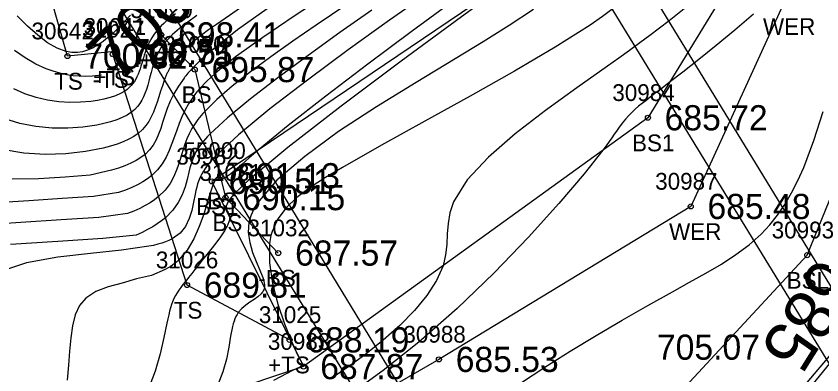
# Model space of a CAD drawing. Extents: x 1376587 to 1378239, y 1000335 to 1003031.
# Drawn here: x 1377325.31 to 1377373.31, y 1001668.9 to 1001690.3 of the extents above; entities that cross this region are included whole.
import ezdxf

# ---------------------------------------------------------------- set-up
doc = ezdxf.new("R2010")
doc.units = 0
for name, color, linetype in [('RD_DTM_BkLn2', 7, 'Continuous'), ('RD_DTM_BkLn_txCode', 7, 'Continuous'), ('RD_DTM_Major1', 7, 'Continuous'), ('RD_DTM_Major1_Lbl', 7, 'Continuous'), ('RD_DTM_Minor1', 7, 'Continuous'), ('RD_EX_Bridge', 7, 'Continuous'), ('RD_EX_H2O', 7, 'Continuous'), ('RD_EX_H2O_txCode', 7, 'Continuous'), ('RD_EX_TX_DV_Prop_ELEV', 7, 'Continuous'), ('RD_EX_TX_H2O_ELEV', 7, 'Continuous'), ('RD_EX_TX_Misc_ELEV', 7, 'Continuous'), ('RD_SMD_Locator', 7, 'Continuous')]:
    doc.layers.add(name, color=color, linetype=linetype)

msp = doc.modelspace()

# ---------------------------------------------------------------- linework, layer by layer
at = {"layer": 'RD_DTM_BkLn2'}
for points in [[(1377331.185, 1001688.178), (1377328.363, 1001687.912), (1377326.336, 1001695.068), (1377322.001, 1001703.779), (1377308.607, 1001727.47), (1377286.368, 1001761.867), (1377261.456, 1001806.931)], [(1377365.624, 1001716.092), (1377370.663, 1001706.746), (1377362.502, 1001698.7), (1377359.368, 1001695.61), (1377337.465, 1001680.779), (1377336.97, 1001680.444), (1377342.423, 1001669.398)], [(1377322.969, 1001642.525), (1377338.521, 1001652.749), (1377349.324, 1001661.46), (1377362.701, 1001665.53), (1377372.438, 1001676.042), (1377380.468, 1001695.811), (1377383.451, 1001707.403)], [(1377333.955, 1001689.179), (1377335.945, 1001687.109), (1377337.465, 1001680.779), (1377337.779, 1001679.474), (1377340.925, 1001676.168)], [(1377341.6, 1001670.994), (1377335.487, 1001674.258), (1377331.067, 1001688.02)]]:
    msp.add_lwpolyline(points, dxfattribs=at)
at = {"layer": 'RD_DTM_Major1'}
for points in [[(1377355.023, 1001692.574), (1377351.835, 1001690.259), (1377348.253, 1001687.62), (1377344.676, 1001684.93), (1377341.501, 1001682.461), (1377339.128, 1001680.486), (1377338.853, 1001680.237), (1377338.608, 1001680.007), (1377338.396, 1001679.797), (1377338.217, 1001679.606), (1377338.071, 1001679.434), (1377337.962, 1001679.282), (1377337.893, 1001679.161), (1377337.85, 1001679.054), (1377337.829, 1001678.959), (1377337.827, 1001678.874), (1377337.84, 1001678.797), (1377337.863, 1001678.725), (1377337.895, 1001678.656), (1377337.93, 1001678.588), (1377337.966, 1001678.52), (1377337.997, 1001678.45), (1377338.02, 1001678.375), (1377338.032, 1001678.293), (1377338.032, 1001678.262), (1377338.031, 1001678.229), (1377338.027, 1001678.195), (1377338.021, 1001678.159), (1377338.014, 1001678.123), (1377338.005, 1001678.086), (1377337.895, 1001677.806), (1377337.715, 1001677.486), (1377337.481, 1001677.135), (1377337.206, 1001676.761), (1377336.905, 1001676.375), (1377336.592, 1001675.983), (1377336.377, 1001675.715), (1377336.166, 1001675.452), (1377335.961, 1001675.196), (1377335.765, 1001674.95), (1377335.581, 1001674.717), (1377335.409, 1001674.501), (1377335.381, 1001674.465), (1377335.353, 1001674.43), (1377335.326, 1001674.395), (1377335.299, 1001674.36), (1377335.272, 1001674.326), (1377335.246, 1001674.293), (1377335.119, 1001674.124), (1377335.002, 1001673.96), (1377334.896, 1001673.797), (1377334.799, 1001673.631), (1377334.711, 1001673.456), (1377334.631, 1001673.268), (1377334.567, 1001673.092), (1377334.508, 1001672.902), (1377334.451, 1001672.697), (1377334.397, 1001672.477), (1377334.342, 1001672.24), (1377334.287, 1001671.985), (1377334.108, 1001671.137), (1377333.882, 1001670.169), (1377333.582, 1001669.12), (1377333.179, 1001668.032)], [(1377343.945, 1001691.663), (1377341.876, 1001690.298), (1377339.997, 1001689.022), (1377339.184, 1001688.45), (1377338.442, 1001687.907), (1377337.772, 1001687.39), (1377337.178, 1001686.894), (1377336.661, 1001686.417), (1377336.223, 1001685.953), (1377336.15, 1001685.868), (1377336.08, 1001685.783), (1377336.012, 1001685.699), (1377335.947, 1001685.614), (1377335.885, 1001685.53), (1377335.824, 1001685.445), (1377335.575, 1001685.06), (1377335.364, 1001684.673), (1377335.182, 1001684.286), (1377335.022, 1001683.897), (1377334.877, 1001683.506), (1377334.738, 1001683.113), (1377334.591, 1001682.698), (1377334.429, 1001682.286), (1377334.241, 1001681.883), (1377334.013, 1001681.495), (1377333.734, 1001681.129), (1377333.389, 1001680.789), (1377333.135, 1001680.592), (1377332.85, 1001680.408), (1377332.535, 1001680.234), (1377332.191, 1001680.071), (1377331.817, 1001679.917), (1377331.414, 1001679.771), (1377329.914, 1001679.539), (1377328.049, 1001679.415), (1377326.06, 1001679.286), (1377324.131, 1001679.161)], [(1377330.384, 1001686.776), (1377330.22, 1001686.749), (1377329.852, 1001686.713), (1377329.463, 1001686.701), (1377329.091, 1001686.711), (1377328.707, 1001686.745), (1377328.315, 1001686.804), (1377327.915, 1001686.891), (1377327.51, 1001687.006), (1377327.102, 1001687.153), (1377326.471, 1001687.442), (1377325.839, 1001687.806), (1377325.206, 1001688.243)], [(1377355.359, 1001668.403), (1377356.808, 1001669.364), (1377358.319, 1001670.32), (1377359.864, 1001671.26), (1377361.413, 1001672.172), (1377362.938, 1001673.044), (1377364.411, 1001673.866), (1377365.431, 1001674.426), (1377366.403, 1001674.971), (1377367.321, 1001675.514), (1377368.178, 1001676.073), (1377368.969, 1001676.664), (1377369.689, 1001677.303), (1377370.202, 1001677.849), (1377370.672, 1001678.438), (1377371.104, 1001679.072), (1377371.503, 1001679.756), (1377371.875, 1001680.49), (1377372.225, 1001681.28), (1377372.825, 1001682.875), (1377373.386, 1001684.602)]]:
    msp.add_lwpolyline(points, dxfattribs=at)
at = {"layer": 'RD_DTM_Minor1'}
for points in [[(1377349.9, 1001691.702), (1377347.559, 1001690.057), (1377345.093, 1001688.284), (1377342.663, 1001686.484), (1377340.428, 1001684.76), (1377338.549, 1001683.213), (1377337.185, 1001681.946), (1377337, 1001681.748), (1377336.837, 1001681.561), (1377336.694, 1001681.384), (1377336.569, 1001681.214), (1377336.461, 1001681.05), (1377336.367, 1001680.889), (1377336.268, 1001680.691), (1377336.186, 1001680.494), (1377336.118, 1001680.296), (1377336.062, 1001680.097), (1377336.014, 1001679.894), (1377335.972, 1001679.686), (1377335.883, 1001679.201), (1377335.778, 1001678.706), (1377335.624, 1001678.232), (1377335.401, 1001677.762), (1377335.069, 1001677.354), (1377334.601, 1001677.016), (1377334.412, 1001676.923), (1377334.204, 1001676.838), (1377333.98, 1001676.762), (1377333.74, 1001676.692), (1377333.483, 1001676.629), (1377333.211, 1001676.572), (1377331.591, 1001676.339), (1377329.731, 1001676.151), (1377327.79, 1001675.928), (1377325.928, 1001675.59), (1377324.303, 1001675.055)], [(1377345.01, 1001690.998), (1377343.186, 1001689.766), (1377341.791, 1001688.804), (1377340.474, 1001687.867), (1377339.262, 1001686.968), (1377338.184, 1001686.119), (1377337.268, 1001685.331), (1377336.543, 1001684.617), (1377336.432, 1001684.493), (1377336.327, 1001684.372), (1377336.229, 1001684.252), (1377336.138, 1001684.135), (1377336.052, 1001684.019), (1377335.973, 1001683.904), (1377335.779, 1001683.592), (1377335.618, 1001683.283), (1377335.482, 1001682.975), (1377335.365, 1001682.665), (1377335.261, 1001682.35), (1377335.163, 1001682.03), (1377335.035, 1001681.604), (1377334.888, 1001681.172), (1377334.708, 1001680.741), (1377334.476, 1001680.319), (1377334.177, 1001679.913), (1377333.793, 1001679.532), (1377333.555, 1001679.345), (1377333.288, 1001679.166), (1377332.995, 1001678.995), (1377332.674, 1001678.831), (1377332.326, 1001678.673), (1377331.951, 1001678.521), (1377330.227, 1001678.287), (1377327.982, 1001678.142), (1377325.583, 1001677.985), (1377323.221, 1001677.833)], [(1377338.987, 1001691), (1377337.24, 1001689.806), (1377336.775, 1001689.472), (1377336.349, 1001689.156), (1377335.965, 1001688.856), (1377335.621, 1001688.57), (1377335.318, 1001688.296), (1377335.058, 1001688.032), (1377334.91, 1001687.863), (1377334.778, 1001687.698), (1377334.661, 1001687.534), (1377334.557, 1001687.373), (1377334.464, 1001687.211), (1377334.38, 1001687.05), (1377334.357, 1001687.004), (1377334.335, 1001686.958), (1377334.314, 1001686.912), (1377334.293, 1001686.866), (1377334.273, 1001686.82), (1377334.253, 1001686.774), (1377334.129, 1001686.458), (1377334.017, 1001686.139), (1377333.913, 1001685.817), (1377333.812, 1001685.493), (1377333.708, 1001685.17), (1377333.596, 1001684.848), (1377333.485, 1001684.566), (1377333.359, 1001684.29), (1377333.211, 1001684.022), (1377333.036, 1001683.767), (1377332.828, 1001683.527), (1377332.581, 1001683.305), (1377332.318, 1001683.12), (1377332.019, 1001682.952), (1377331.687, 1001682.799), (1377331.322, 1001682.662), (1377330.926, 1001682.537), (1377330.5, 1001682.426), (1377329.439, 1001682.218), (1377328.272, 1001682.088), (1377327.032, 1001682.054), (1377325.756, 1001682.135), (1377324.48, 1001682.35)], [(1377340.748, 1001691.063), (1377338.499, 1001689.47), (1377336.674, 1001688.012), (1377336.52, 1001687.875), (1377336.371, 1001687.74), (1377336.229, 1001687.606), (1377336.093, 1001687.475), (1377335.963, 1001687.346), (1377335.839, 1001687.219), (1377335.762, 1001687.136), (1377335.687, 1001687.054), (1377335.615, 1001686.973), (1377335.545, 1001686.893), (1377335.478, 1001686.813), (1377335.413, 1001686.734), (1377335.395, 1001686.712), (1377335.377, 1001686.689), (1377335.36, 1001686.667), (1377335.342, 1001686.645), (1377335.325, 1001686.623), (1377335.308, 1001686.601), (1377334.971, 1001686.123), (1377334.702, 1001685.662), (1377334.487, 1001685.216), (1377334.313, 1001684.784), (1377334.167, 1001684.364), (1377334.036, 1001683.955), (1377333.921, 1001683.6), (1377333.797, 1001683.256), (1377333.652, 1001682.926), (1377333.476, 1001682.612), (1377333.257, 1001682.318), (1377332.985, 1001682.047), (1377332.739, 1001681.859), (1377332.456, 1001681.686), (1377332.14, 1001681.525), (1377331.789, 1001681.375), (1377331.406, 1001681.237), (1377330.992, 1001681.108), (1377329.713, 1001680.805), (1377328.223, 1001680.696), (1377326.641, 1001680.595), (1377325.08, 1001680.575)], [(1377351.355, 1001691.217), (1377348.847, 1001689.368), (1377346.252, 1001687.429), (1377343.748, 1001685.523), (1377341.511, 1001683.773), (1377339.717, 1001682.304), (1377339.192, 1001681.85), (1377338.748, 1001681.458), (1377338.378, 1001681.134), (1377338.076, 1001680.881), (1377337.835, 1001680.706), (1377337.649, 1001680.613), (1377337.622, 1001680.606), (1377337.596, 1001680.601), (1377337.572, 1001680.599), (1377337.549, 1001680.6), (1377337.527, 1001680.603), (1377337.506, 1001680.61), (1377337.482, 1001680.626), (1377337.458, 1001680.643), (1377337.434, 1001680.66), (1377337.41, 1001680.676), (1377337.387, 1001680.693), (1377337.363, 1001680.71), (1377337.322, 1001680.717), (1377337.28, 1001680.702), (1377337.238, 1001680.665), (1377337.194, 1001680.608), (1377337.149, 1001680.531), (1377337.102, 1001680.433), (1377337.068, 1001680.351), (1377337.032, 1001680.259), (1377336.996, 1001680.157), (1377336.959, 1001680.046), (1377336.92, 1001679.926), (1377336.88, 1001679.798), (1377336.697, 1001679.189), (1377336.479, 1001678.489), (1377336.212, 1001677.748), (1377335.886, 1001677.014), (1377335.487, 1001676.334), (1377335.005, 1001675.758), (1377334.88, 1001675.645), (1377334.751, 1001675.539), (1377334.616, 1001675.44), (1377334.477, 1001675.348), (1377334.334, 1001675.262), (1377334.187, 1001675.182), (1377333.371, 1001674.84), (1377332.487, 1001674.626), (1377331.623, 1001674.372), (1377330.791, 1001674.15), (1377330.052, 1001673.87), (1377329.455, 1001673.484), (1377329.081, 1001673.033), (1377328.825, 1001672.478), (1377328.659, 1001671.832), (1377328.556, 1001671.107), (1377328.487, 1001670.317), (1377328.427, 1001669.474), (1377328.349, 1001668.592)], [(1377346.499, 1001690.644), (1377344.592, 1001689.314), (1377342.695, 1001687.957), (1377340.891, 1001686.624), (1377339.264, 1001685.367), (1377337.894, 1001684.235), (1377336.864, 1001683.281), (1377336.716, 1001683.127), (1377336.582, 1001682.98), (1377336.461, 1001682.838), (1377336.351, 1001682.701), (1377336.253, 1001682.568), (1377336.164, 1001682.438), (1377336.021, 1001682.198), (1377335.905, 1001681.962), (1377335.81, 1001681.726), (1377335.73, 1001681.488), (1377335.662, 1001681.245), (1377335.599, 1001680.993), (1377335.496, 1001680.561), (1377335.372, 1001680.109), (1377335.203, 1001679.645), (1377334.966, 1001679.179), (1377334.639, 1001678.719), (1377334.197, 1001678.274), (1377333.97, 1001678.091), (1377333.718, 1001677.913), (1377333.441, 1001677.738), (1377333.14, 1001677.567), (1377332.814, 1001677.4), (1377332.464, 1001677.236), (1377330.469, 1001677.034), (1377327.793, 1001676.859), (1377324.963, 1001676.675)], [(1377356.122, 1001690.699), (1377354.688, 1001689.747), (1377353.132, 1001688.769), (1377351.468, 1001687.754), (1377349.137, 1001686.348), (1377346.773, 1001684.892), (1377344.512, 1001683.415), (1377342.508, 1001681.936), (1377340.828, 1001680.514), (1377339.675, 1001679.147), (1377339.555, 1001678.954), (1377339.45, 1001678.761), (1377339.36, 1001678.57), (1377339.284, 1001678.381), (1377339.224, 1001678.191), (1377339.179, 1001678.003), (1377339.138, 1001677.39), (1377339.224, 1001676.789), (1377339.396, 1001676.208), (1377339.611, 1001675.66), (1377339.828, 1001675.155), (1377340.005, 1001674.704), (1377340.04, 1001674.592), (1377340.068, 1001674.485), (1377340.089, 1001674.383), (1377340.101, 1001674.287), (1377340.104, 1001674.195), (1377340.097, 1001674.109), (1377340.083, 1001674.039), (1377340.06, 1001673.973), (1377340.031, 1001673.911), (1377339.995, 1001673.851), (1377339.952, 1001673.793), (1377339.904, 1001673.738), (1377339.713, 1001673.568), (1377339.484, 1001673.406), (1377339.235, 1001673.241), (1377338.983, 1001673.063), (1377338.746, 1001672.862), (1377338.542, 1001672.627), (1377338.466, 1001672.51), (1377338.399, 1001672.384), (1377338.34, 1001672.25), (1377338.288, 1001672.107), (1377338.242, 1001671.957), (1377338.2, 1001671.799), (1377338.082, 1001671.211), (1377337.97, 1001670.552), (1377337.83, 1001669.839), (1377337.626, 1001669.089), (1377337.32, 1001668.318)], [(1377360.883, 1001690.752), (1377360.234, 1001690.27), (1377359.5, 1001689.762), (1377357.423, 1001688.445), (1377354.989, 1001687.015), (1377352.352, 1001685.526), (1377349.664, 1001684.036), (1377347.08, 1001682.602), (1377344.751, 1001681.279), (1377343.73, 1001680.672), (1377342.822, 1001680.084), (1377342.039, 1001679.491), (1377341.392, 1001678.872), (1377340.894, 1001678.203), (1377340.555, 1001677.46), (1377340.519, 1001677.343), (1377340.487, 1001677.224), (1377340.459, 1001677.103), (1377340.434, 1001676.979), (1377340.413, 1001676.852), (1377340.397, 1001676.723), (1377340.394, 1001675.59), (1377340.584, 1001674.359), (1377340.906, 1001673.114), (1377341.299, 1001671.941), (1377341.702, 1001670.923), (1377342.052, 1001670.148), (1377342.071, 1001670.107), (1377342.091, 1001670.068), (1377342.11, 1001670.03), (1377342.128, 1001669.993), (1377342.146, 1001669.959), (1377342.163, 1001669.925), (1377342.195, 1001669.863), (1377342.225, 1001669.807), (1377342.253, 1001669.756), (1377342.278, 1001669.71), (1377342.3, 1001669.67), (1377342.319, 1001669.633), (1377342.345, 1001669.582), (1377342.362, 1001669.539), (1377342.371, 1001669.505), (1377342.37, 1001669.476), (1377342.36, 1001669.452), (1377342.34, 1001669.43), (1377342.299, 1001669.404), (1377342.24, 1001669.377), (1377342.163, 1001669.345), (1377342.064, 1001669.305), (1377341.945, 1001669.255), (1377341.803, 1001669.19), (1377340.641, 1001668.561)], [(1377365.104, 1001690.732), (1377364.204, 1001690.023), (1377363.639, 1001689.588), (1377363.059, 1001689.147), (1377362.462, 1001688.7), (1377361.846, 1001688.245), (1377361.208, 1001687.781), (1377360.546, 1001687.305), (1377358.72, 1001686.012), (1377356.843, 1001684.66), (1377355.042, 1001683.277), (1377353.442, 1001681.89), (1377352.171, 1001680.527), (1377351.355, 1001679.215), (1377351.142, 1001678.566), (1377351.037, 1001677.933), (1377350.991, 1001677.307), (1377350.957, 1001676.682), (1377350.89, 1001676.053), (1377350.741, 1001675.413), (1377350.359, 1001674.537), (1377349.781, 1001673.643), (1377349.038, 1001672.743), (1377348.161, 1001671.85), (1377347.182, 1001670.977), (1377346.132, 1001670.136), (1377345.121, 1001669.396), (1377344.078, 1001668.685)], [(1377336.081, 1001690.335), (1377335.526, 1001689.936), (1377335.038, 1001689.557), (1377334.621, 1001689.195), (1377334.276, 1001688.845), (1377334.091, 1001688.621), (1377333.934, 1001688.4), (1377333.803, 1001688.182), (1377333.694, 1001687.966), (1377333.602, 1001687.752), (1377333.523, 1001687.539), (1377333.503, 1001687.479), (1377333.484, 1001687.419), (1377333.465, 1001687.359), (1377333.447, 1001687.299), (1377333.43, 1001687.239), (1377333.412, 1001687.179), (1377333.344, 1001686.926), (1377333.278, 1001686.674), (1377333.213, 1001686.423), (1377333.144, 1001686.175), (1377333.068, 1001685.931), (1377332.982, 1001685.69), (1377332.894, 1001685.482), (1377332.793, 1001685.28), (1377332.674, 1001685.085), (1377332.534, 1001684.9), (1377332.37, 1001684.725), (1377332.177, 1001684.563), (1377331.921, 1001684.394), (1377331.626, 1001684.243), (1377331.296, 1001684.108), (1377330.933, 1001683.99), (1377330.539, 1001683.888), (1377330.119, 1001683.8), (1377329.286, 1001683.678), (1377328.39, 1001683.615), (1377327.449, 1001683.623), (1377326.485, 1001683.713), (1377325.517, 1001683.899), (1377324.564, 1001684.19)], [(1377334.793, 1001690.441), (1377334.599, 1001690.289), (1377334.419, 1001690.141), (1377334.252, 1001689.997), (1377334.098, 1001689.856), (1377333.956, 1001689.717), (1377333.825, 1001689.58), (1377333.7, 1001689.437), (1377333.586, 1001689.294), (1377333.483, 1001689.152), (1377333.39, 1001689.01), (1377333.306, 1001688.868), (1377333.231, 1001688.726), (1377333.159, 1001688.575), (1377333.095, 1001688.424), (1377333.037, 1001688.272), (1377332.984, 1001688.119), (1377332.935, 1001687.966), (1377332.888, 1001687.813), (1377332.872, 1001687.756), (1377332.855, 1001687.699), (1377332.839, 1001687.642), (1377332.822, 1001687.585), (1377332.806, 1001687.527), (1377332.789, 1001687.47), (1377332.742, 1001687.311), (1377332.692, 1001687.153), (1377332.636, 1001686.995), (1377332.575, 1001686.839), (1377332.506, 1001686.686), (1377332.428, 1001686.535), (1377332.349, 1001686.404), (1377332.261, 1001686.277), (1377332.161, 1001686.155), (1377332.047, 1001686.037), (1377331.919, 1001685.925), (1377331.774, 1001685.82), (1377331.519, 1001685.675), (1377331.226, 1001685.547), (1377330.899, 1001685.436), (1377330.541, 1001685.343), (1377330.156, 1001685.267), (1377329.747, 1001685.21), (1377329.143, 1001685.161), (1377328.508, 1001685.154), (1377327.852, 1001685.196), (1377327.181, 1001685.291), (1377326.504, 1001685.447), (1377325.829, 1001685.669), (1377325.17, 1001685.959)], [(1377332.114, 1001690.353), (1377331.796, 1001690.012), (1377331.485, 1001689.687), (1377331.178, 1001689.383), (1377331.006, 1001689.222), (1377330.833, 1001689.069), (1377330.659, 1001688.925), (1377330.483, 1001688.79), (1377330.305, 1001688.663), (1377330.124, 1001688.546), (1377329.847, 1001688.39), (1377329.561, 1001688.262), (1377329.263, 1001688.169), (1377328.953, 1001688.119), (1377328.628, 1001688.12), (1377328.288, 1001688.178), (1377327.749, 1001688.38), (1377327.181, 1001688.711), (1377326.59, 1001689.153), (1377325.986, 1001689.691), (1377325.376, 1001690.308)], [(1377369.228, 1001690.414), (1377368.12, 1001689.463), (1377367.021, 1001688.552), (1377365.975, 1001687.708), (1377365.027, 1001686.958), (1377364.221, 1001686.332), (1377363.69, 1001685.925), (1377363.464, 1001685.753), (1377363.26, 1001685.598), (1377363.075, 1001685.457), (1377362.812, 1001685.255), (1377362.549, 1001685.05), (1377362.468, 1001684.984), (1377362.389, 1001684.92), (1377362.191, 1001684.75), (1377361.999, 1001684.573), (1377361.808, 1001684.379), (1377361.613, 1001684.159), (1377361.409, 1001683.906), (1377361.19, 1001683.61), (1377361.069, 1001683.438), (1377360.939, 1001683.25), (1377360.797, 1001683.044), (1377360.638, 1001682.818), (1377360.46, 1001682.569), (1377360.258, 1001682.295), (1377359.145, 1001680.885), (1377357.643, 1001679.122), (1377355.828, 1001677.12), (1377353.78, 1001674.996), (1377351.576, 1001672.866), (1377349.294, 1001670.847), (1377347.174, 1001669.16), (1377345.073, 1001667.645)]]:
    msp.add_lwpolyline(points, dxfattribs=at)
at = {"layer": 'RD_EX_Bridge'}
for points in [[(1377391.499, 1001645.129), (1377368.188, 1001630.936), (1377328.998, 1001694.929), (1377352.485, 1001709.161), (1377391.541, 1001645.169)], [(1377350.392, 1001707.762), (1377389.063, 1001644.517)], [(1377331.327, 1001695.905), (1377370.084, 1001632.15)]]:
    msp.add_lwpolyline(points, dxfattribs=at)
at = {"layer": 'RD_EX_H2O'}
for points in [[(1377371.252, 1001717.109), (1377370.663, 1001706.746), (1377369.728, 1001695.357), (1377362.942, 1001684.236), (1377342.423, 1001669.398), (1377312.741, 1001659.466), (1377279.928, 1001621.341), (1377233.434, 1001598.677), (1377169.941, 1001585.879), (1377114.813, 1001581.379), (1377057.35, 1001560.459), (1377030.227, 1001561.127), (1376975.162, 1001566.792), (1376927.948, 1001589.938)], [(1377375.48, 1001712.375), (1377377.18, 1001695.925), (1377371.091, 1001691.175), (1377365.495, 1001678.948), (1377350.495, 1001669.827), (1377334.456, 1001660.576)], [(1377385.629, 1001693.938), (1377384.621, 1001693.635), (1377383.547, 1001681.612), (1377370.643, 1001666.371), (1377351.116, 1001654.803), (1377346.874, 1001651.39)], [(1377396.047, 1001693.167), (1377388.971, 1001691.891), (1377383.547, 1001681.612), (1377370.954, 1001666.151), (1377345.792, 1001650.036), (1377349.116, 1001628.131), (1377334.126, 1001625.317), (1377311.323, 1001589.505), (1377259.373, 1001541.156), (1377186.141, 1001542.199), (1377119.382, 1001530.527), (1377065.136, 1001518.284), (1377035.175, 1001514.747), (1376967.402, 1001521.021), (1376926.832, 1001536.774)]]:
    msp.add_lwpolyline(points, dxfattribs=at)
at = {"layer": 'RD_SMD_Locator'}
for centre in [(1377333.955, 1001689.179), (1377331.067, 1001688.02), (1377331.185, 1001688.178), (1377328.363, 1001687.912), (1377335.945, 1001687.109), (1377362.942, 1001684.236), (1377337.465, 1001680.779), (1377336.97, 1001680.444), (1377337.779, 1001679.474), (1377365.495, 1001678.948), (1377340.925, 1001676.168), (1377372.438, 1001676.042), (1377335.487, 1001674.258), (1377341.6, 1001670.994), (1377350.495, 1001669.827), (1377342.423, 1001669.398)]:
    msp.add_circle(centre, 0.15, dxfattribs=at)

# ---------------------------------------------------------------- texts
at = {"layer": 'RD_DTM_BkLn_txCode'}
for s, p in [('31029', (1377332.12, 1001690.179)), ('31027', (1377329.232, 1001689.02)), ('30641', (1377329.327, 1001689.178)), ('30642', (1377326.221, 1001688.912)), ('31030', (1377334.071, 1001688.109)), ('+BS', (1377332.687, 1001687.179)), ('+TS', (1377329.902, 1001686.178)), ('TS', (1377327.568, 1001685.912)), ('-TS', (1377329.862, 1001686.02)), ('30984', (1377360.824, 1001685.236)), ('BS', (1377335.165, 1001685.109)), ('BS1', (1377361.997, 1001682.236)), ('30982', (1377334.852, 1001681.444)), ('55000', (1377335.269, 1001681.779)), ('31031', (1377336.228, 1001680.474)), ('BS', (1377336.686, 1001678.779)), ('BS1', (1377336.025, 1001678.444)), ('BS', (1377336.999, 1001677.474)), ('31032', (1377339.09, 1001677.168)), ('30993', (1377370.32, 1001677.042)), ('31026', (1377333.629, 1001675.258)), ('-BS', (1377339.736, 1001674.168)), ('BSL', (1377371.21, 1001674.042)), ('TS', (1377334.692, 1001672.258)), ('31025', (1377339.766, 1001671.994)), ('30983', (1377340.305, 1001670.398)), ('+TS', (1377340.317, 1001668.994))]:
    msp.add_text(s, height=1, dxfattribs=at).set_placement(p)
at = {"layer": 'RD_DTM_Major1_Lbl'}
for s, rotation, p in [('700', 44.8097, (1377331.392, 1001686.21)), ('685', 237.9788, (1377373.115, 1001676.102))]:
    msp.add_text(s, height=3, rotation=rotation, dxfattribs=at).set_placement(p)
at = {"layer": 'RD_EX_H2O_txCode'}
for s, p in [('WER', (1377369.8, 1001689.175)), ('30987', (1377363.377, 1001679.948)), ('WER', (1377364.204, 1001676.948)), ('30988', (1377348.377, 1001670.827))]:
    msp.add_text(s, height=1, dxfattribs=at).set_placement(p)
at = {"layer": 'RD_EX_TX_DV_Prop_ELEV'}
msp.add_text('705.07', height=1.5, dxfattribs=at).set_placement((1377363.483, 1001669.808))
at = {"layer": 'RD_EX_TX_H2O_ELEV'}
for s, p in [('685.48', (1377366.495, 1001678.198)), ('685.53', (1377351.495, 1001669.077))]:
    msp.add_text(s, height=1.5, dxfattribs=at).set_placement(p)
at = {"layer": 'RD_EX_TX_Misc_ELEV'}
for s, p in [('698.41', (1377334.955, 1001688.429)), ('700.92', (1377329.363, 1001687.162)), ('700.75', (1377332.067, 1001687.27)), ('700.51', (1377332.185, 1001687.428)), ('695.87', (1377336.945, 1001686.359)), ('685.72', (1377363.942, 1001683.486)), ('691.13', (1377338.465, 1001680.029)), ('690.51', (1377337.97, 1001679.694)), ('690.15', (1377338.779, 1001678.724)), ('687.57', (1377341.925, 1001675.418)), ('689.81', (1377336.487, 1001673.508)), ('688.19', (1377342.6, 1001670.244)), ('687.87', (1377343.423, 1001668.648))]:
    msp.add_text(s, height=1.5, dxfattribs=at).set_placement(p)

doc.saveas('drawing.dxf')
